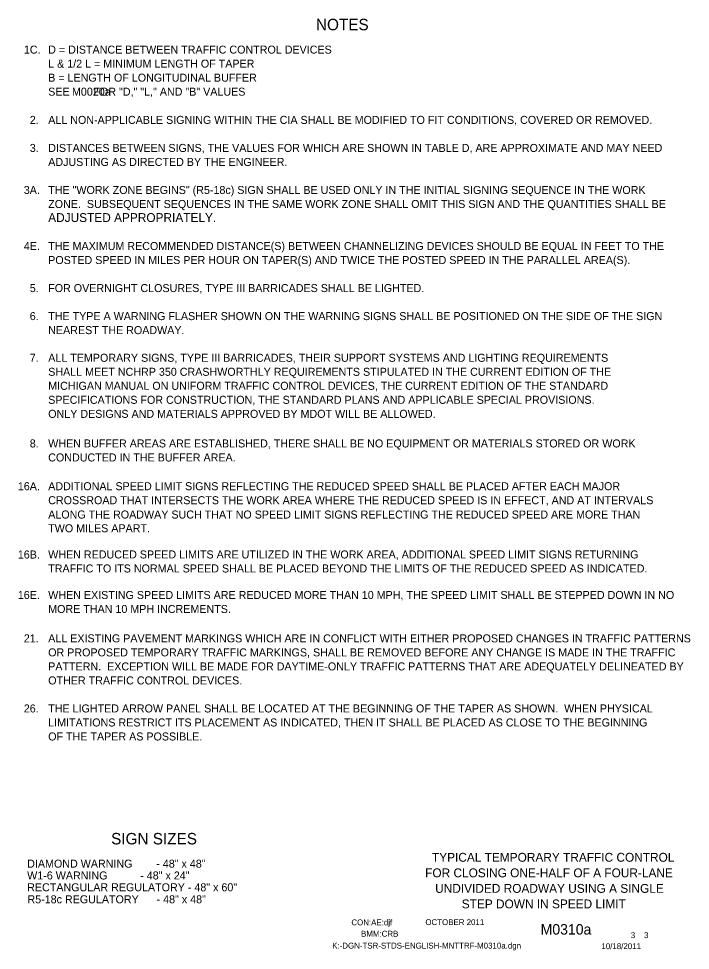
# Model space of a CAD drawing. Extents: x 16473 to 19504, y 4850 to 6919.
# Drawn here: x 18800 to 19504, y 5932 to 6909 of the extents above; entities that cross this region are included whole.
import ezdxf

# ---------------------------------------------------------------- set-up
doc = ezdxf.new("R2010")
doc.units = 0
for name, color, linetype in [('BORDER', 7, 'Continuous'), ('BORDER_SIGNAL_WO', 7, 'Continuous'), ('TYPICAL_TEXT_DIMEN_PR', 7, 'Continuous')]:
    doc.layers.add(name, color=color, linetype=linetype)

msp = doc.modelspace()

# ---------------------------------------------------------------- linework, layer by layer
at = {"layer": 'BORDER'}
msp.add_line((18938.25, 6055), (18938.25, 6055), dxfattribs=at)

# ---------------------------------------------------------------- texts
at = {"layer": 'BORDER_SIGNAL_WO'}
for s, height, p in [('TYPICAL TEMPORARY TRAFFIC CONTROL', 9.3, (19233.21, 6024.8)), ('FOR CLOSING ONE-HALF OF A FOUR-LANE', 9.3, (19226.06, 6008.5)), ('UNDIVIDED ROADWAY USING A SINGLE', 9.3, (19236.56, 5992.2)), ('STEP DOWN IN SPEED LIMIT', 9.3, (19264.42, 5975.9)), ('CON:AE:djf', 6.2, (19148.69, 5958.06)), ('    OCTOBER 2011    ', 6.2, (19217.08, 5958.34)), ('BMM:CRB   ', 6.2, (19158.81, 5946.17)), ('    M0310a   ', 11, (19330.86, 5948.38)), (' 3    3 ', 6.2, (19439.45, 5944.7)), ('K:-DGN-TSR-STDS-ENGLISH-MNTTRF-M0310a.dgn        ', 6.2, (19128.55, 5933.71)), ('10/18/2011    ', 6.2, (19410.93, 5933.13))]:
    msp.add_text(s, height=height, dxfattribs=at).set_placement(p)
at = {"layer": 'TYPICAL_TEXT_DIMEN_PR'}
for s, height, p in [('NOTES', 12, (19111.55, 6897)), ('1C.', 8.4, (18805.19, 6872.47)), ('D = DISTANCE BETWEEN TRAFFIC CONTROL DEVICES', 8.4, (18830.7, 6872.47)), ('L & 1/2 L = MINIMUM LENGTH OF TAPER', 8.4, (18830.7, 6857.77)), ('B = LENGTH OF LONGITUDINAL BUFFER', 8.4, (18830.7, 6843.07)), ('SEE        FOR "D," "L," AND "B" VALUES', 8.4, (18830.7, 6828.37)), ('M0020a', 8.4, (18855.62, 6828.37)), ('2.', 8.4, (18811.39, 6798.75)), ('ALL NON-APPLICABLE SIGNING WITHIN THE CIA SHALL BE MODIFIED TO FIT CONDITIONS, COVERED OR REMOVED.', 8.4, (18830.7, 6798.75)), ('3.', 8.4, (18811.39, 6769.35)), ('DISTANCES BETWEEN SIGNS, THE VALUES FOR WHICH ARE SHOWN IN TABLE D, ARE APPROXIMATE AND MAY NEED', 8.4, (18830.7, 6769.35)), ('ADJUSTING AS DIRECTED BY THE ENGINEER.', 8.4, (18830.7, 6754.65)), ('THE "WORK ZONE BEGINS" (R5-18c) SIGN SHALL BE USED ONLY IN THE INITIAL SIGNING SEQUENCE IN THE WORK', 8.4, (18830.7, 6725.25)), ('3A.', 8.4, (18805.09, 6725.25)), ('ZONE.  SUBSEQUENT SEQUENCES IN THE SAME WORK ZONE SHALL OMIT THIS SIGN AND THE QUANTITIES SHALL BE', 8.4, (18830.7, 6710.55)), ('ADJUSTED APPROPRIATELY.', 9.3, (18830.7, 6695.85)), ('THE MAXIMUM RECOMMENDED DISTANCE(S) BETWEEN CHANNELIZING DEVICES SHOULD BE EQUAL IN FEET TO THE', 8.4, (18830.7, 6666.45)), ('4E.', 8.4, (18805.13, 6666.45)), ('POSTED SPEED IN MILES PER HOUR ON TAPER(S) AND TWICE THE POSTED SPEED IN THE PARALLEL AREA(S).', 8.4, (18830.7, 6651.75)), ('5.', 8.4, (18811.39, 6622.35)), ('FOR OVERNIGHT CLOSURES, TYPE III BARRICADES SHALL BE LIGHTED.', 8.4, (18830.7, 6622.35)), ('6.', 8.4, (18811.34, 6592.95)), ('THE TYPE A WARNING FLASHER SHOWN ON THE WARNING SIGNS SHALL BE POSITIONED ON THE SIDE OF THE SIGN', 8.4, (18830.7, 6592.95)), ('NEAREST THE ROADWAY.', 8.4, (18830.7, 6578.25)), ('7.', 8.4, (18811.34, 6549.21)), ('ALL TEMPORARY SIGNS, TYPE III BARRICADES, THEIR SUPPORT SYSTEMS AND LIGHTING REQUIREMENTS', 8.4, (18830.7, 6549.23)), ('SHALL MEET NCHRP 350 CRASHWORTHLY REQUIREMENTS STIPULATED IN THE CURRENT EDITION OF THE', 8.4, (18830.7, 6534.53)), ('MICHIGAN MANUAL ON UNIFORM TRAFFIC CONTROL DEVICES, THE CURRENT EDITION OF THE STANDARD', 8.4, (18830.7, 6519.83)), ('SPECIFICATIONS FOR CONSTRUCTION, THE STANDARD PLANS AND APPLICABLE SPECIAL PROVISIONS.', 8.4, (18830.7, 6505.13)), ('ONLY DESIGNS AND MATERIALS APPROVED BY MDOT WILL BE ALLOWED.', 8.4, (18830.7, 6490.43)), ('8.', 8.4, (18811.39, 6459.38)), ('WHEN BUFFER AREAS ARE ESTABLISHED, THERE SHALL BE NO EQUIPMENT OR MATERIALS STORED OR WORK     ', 8.4, (18830.7, 6459.38)), ('CONDUCTED IN THE BUFFER AREA.', 8.4, (18830.7, 6444.68)), ('16A.', 8.4, (18798.84, 6414.51)), ('ADDITIONAL SPEED LIMIT SIGNS REFLECTING THE REDUCED SPEED SHALL BE PLACED AFTER EACH MAJOR', 8.4, (18830.7, 6414.51)), ('CROSSROAD THAT INTERSECTS THE WORK AREA WHERE THE REDUCED SPEED IS IN EFFECT, AND AT INTERVALS', 8.4, (18830.7, 6399.81)), ('ALONG THE ROADWAY SUCH THAT NO SPEED LIMIT SIGNS REFLECTING THE REDUCED SPEED ARE MORE THAN', 8.4, (18830.7, 6384.81)), ('TWO MILES APART.', 8.4, (18830.7, 6370.41)), ('16B.', 8.4, (18798.83, 6342.88)), ('WHEN REDUCED SPEED LIMITS ARE UTILIZED IN THE WORK AREA, ADDITIONAL SPEED LIMIT SIGNS RETURNING', 8.4, (18830.7, 6342.94)), ('TRAFFIC TO ITS NORMAL SPEED SHALL BE PLACED BEYOND THE LIMITS OF THE REDUCED SPEED AS INDICATED.', 8.4, (18830.7, 6328.24)), ('16E.', 8.4, (18798.84, 6300.43)), ('WHEN EXISTING SPEED LIMITS ARE REDUCED MORE THAN 10 MPH, THE SPEED LIMIT SHALL BE STEPPED DOWN IN NO', 8.4, (18830.7, 6300.43)), ('MORE THAN 10 MPH INCREMENTS.', 8.4, (18830.7, 6285.73)), ('21.', 8.4, (18805.13, 6254.9)), ('ALL EXISTING PAVEMENT MARKINGS WHICH ARE IN CONFLICT WITH EITHER PROPOSED CHANGES IN TRAFFIC PATTERNS', 8.4, (18830.7, 6254.9)), ('OR PROPOSED TEMPORARY TRAFFIC MARKINGS, SHALL BE REMOVED BEFORE ANY CHANGE IS MADE IN THE TRAFFIC', 8.4, (18830.7, 6240.2)), ('PATTERN.  EXCEPTION WILL BE MADE FOR DAYTIME-ONLY TRAFFIC PATTERNS THAT ARE ADEQUATELY DELINEATED BY', 8.4, (18830.7, 6225.5)), ('OTHER TRAFFIC CONTROL DEVICES.', 8.4, (18830.7, 6210.8)), ('26.', 8.4, (18805.08, 6181.4)), ('THE LIGHTED ARROW PANEL SHALL BE LOCATED AT THE BEGINNING OF THE TAPER AS SHOWN.  WHEN PHYSICAL', 8.4, (18830.7, 6181.4)), ('LIMITATIONS RESTRICT ITS PLACEMENT AS INDICATED, THEN IT SHALL BE PLACED AS CLOSE TO THE BEGINNING', 8.4, (18830.7, 6166.7)), ('OF THE TAPER AS POSSIBLE.', 8.4, (18830.7, 6152)), ('SIGN SIZES', 12, (18896.69, 6043)), ('DIAMOND WARNING        - 48" x 48"', 8.4, (18808.65, 6018.6)), ('W1-6 WARNING           - 48" x 24"', 8.4, (18808.65, 6006.2)), ('RECTANGULAR REGULATORY - 48" x 60"', 8.4, (18808.65, 5993.8)), ('R5-18c REGULATORY      - 48" x 48"', 8.4, (18808.94, 5981.2))]:
    msp.add_text(s, height=height, dxfattribs=at).set_placement(p)

doc.saveas('drawing.dxf')
